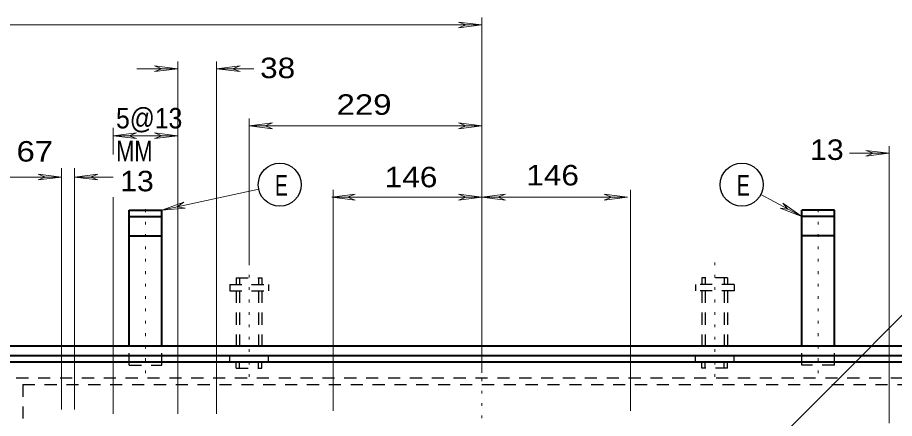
# Model space of a CAD drawing. Extents: x 312583 to 312854, y 144419 to 144597.
# Drawn here: x 312652.93 to 312685.41, y 144562.03 to 144576.9 of the extents above; entities that cross this region are included whole.
import ezdxf

# ---------------------------------------------------------------- set-up
doc = ezdxf.new("R2010")
doc.units = 0
doc.header["$LTSCALE"] = 0.3
doc.linetypes.add('DOTTED', pattern=[1.5, 0.3, -1.2])
doc.linetypes.add('SHORT_DASHED', pattern=[2.7, 1.5, -1.2])
doc.layers.add('1', color=7, linetype='Continuous', lineweight=13)

msp = doc.modelspace()

# ---------------------------------------------------------------- linework, layer by layer
at = {"layer": '1'}
for p, q in [((312670.1353, 144563.7206), (312670.1353, 144576.8996)), ((312652.0419, 144576.6236), (312670.1353, 144576.6236)), ((312669.2689, 144576.731), (312669.5449, 144576.6236)), ((312670.1353, 144576.6236), (312669.2689, 144576.731)), ((312669.2689, 144576.5163), (312669.5449, 144576.6236)), ((312670.1353, 144576.6236), (312669.2689, 144576.5163)), ((312658.8729, 144562.2026), (312658.8729, 144575.2666)), ((312660.3066, 144562.2026), (312660.3066, 144575.2666)), ((312657.3473, 144574.9983), (312658.8729, 144574.9983)), ((312658.0066, 144575.1056), (312658.2826, 144574.9983)), ((312658.8729, 144574.9983), (312658.0066, 144575.1056)), ((312658.0066, 144574.891), (312658.2826, 144574.9983)), ((312658.8729, 144574.9983), (312658.0066, 144574.891)), ((312660.3066, 144574.9983), (312661.1729, 144575.1056)), ((312660.3066, 144574.9983), (312661.6866, 144574.9983)), ((312660.3066, 144574.9983), (312661.1729, 144574.891)), ((312661.1729, 144575.1056), (312660.8969, 144574.9983)), ((312661.1729, 144574.891), (312660.8969, 144574.9983)), ((312661.5103, 144567.8146), (312661.5103, 144573.1506)), ((312661.5103, 144572.8823), (312662.3766, 144572.9896)), ((312662.3766, 144572.9896), (312662.1006, 144572.8823)), ((312669.2689, 144572.9896), (312669.5449, 144572.8823)), ((312670.1353, 144572.8823), (312669.2689, 144572.9896)), ((312656.4733, 144571.8166), (312656.4733, 144572.8133)), ((312656.4733, 144572.5143), (312657.3396, 144572.6216)), ((312657.3396, 144572.6216), (312657.0636, 144572.5143)), ((312658.0066, 144572.6216), (312658.2826, 144572.5143)), ((312658.8729, 144572.5143), (312658.0066, 144572.6216)), ((312661.5103, 144572.8823), (312670.1353, 144572.8823)), ((312661.5103, 144572.8823), (312662.3766, 144572.775)), ((312662.3766, 144572.775), (312662.1006, 144572.8823)), ((312669.2689, 144572.775), (312669.5449, 144572.8823)), ((312670.1353, 144572.8823), (312669.2689, 144572.775)), ((312656.4733, 144572.5143), (312658.8729, 144572.5143)), ((312656.4733, 144572.5143), (312657.3396, 144572.407)), ((312657.3396, 144572.407), (312657.0636, 144572.5143)), ((312658.0066, 144572.407), (312658.2826, 144572.5143)), ((312658.8729, 144572.5143), (312658.0066, 144572.407)), ((312684.3569, 144571.97), (312684.6329, 144571.8626)), ((312685.2233, 144571.8626), (312684.3569, 144571.97)), ((312685.2233, 144561.85), (312685.2233, 144572.131)), ((312683.7513, 144571.8626), (312685.2233, 144571.8626)), ((312684.3569, 144571.7553), (312684.6329, 144571.8626)), ((312685.2233, 144571.8626), (312684.3569, 144571.7553)), ((312654.5566, 144562.356), (312654.5566, 144571.3106)), ((312655.0396, 144562.356), (312655.0396, 144571.3106)), ((312653.6903, 144571.0883), (312653.9663, 144570.981)), ((312654.5566, 144570.981), (312653.6903, 144571.0883)), ((312655.0396, 144570.981), (312655.9059, 144571.0883)), ((312655.9059, 144571.0883), (312655.6299, 144570.981)), ((312652.0419, 144570.981), (312654.5566, 144570.981)), ((312653.6903, 144570.8736), (312653.9663, 144570.981)), ((312654.5566, 144570.981), (312653.6903, 144570.8736)), ((312655.0396, 144570.981), (312656.4733, 144570.981)), ((312655.0396, 144570.981), (312655.9059, 144570.8736)), ((312655.9059, 144570.8736), (312655.6299, 144570.981)), ((312661.8706, 144570.5286), (312658.2749, 144569.7543)), ((312664.5693, 144570.2373), (312665.4356, 144570.3446)), ((312664.6229, 144562.31), (312664.6229, 144570.5056)), ((312665.4356, 144570.3446), (312665.1596, 144570.2373)), ((312669.2689, 144570.3446), (312669.5449, 144570.2373)), ((312670.1353, 144570.2373), (312669.2689, 144570.3446)), ((312670.1353, 144570.2373), (312671.0016, 144570.3446)), ((312671.0016, 144570.3446), (312670.7256, 144570.2373)), ((312674.6586, 144570.3446), (312674.9346, 144570.2373)), ((312675.5249, 144570.2373), (312674.6586, 144570.3446)), ((312675.6399, 144562.31), (312675.6399, 144570.5056)), ((312656.4733, 144562.2026), (312656.4733, 144570.2296)), ((312658.2749, 144569.7543), (312659.0953, 144570.0456)), ((312659.0953, 144570.0456), (312658.8499, 144569.877)), ((312664.5693, 144570.2373), (312665.4356, 144570.13)), ((312665.4356, 144570.13), (312665.1596, 144570.2373)), ((312669.2689, 144570.13), (312669.5449, 144570.2373)), ((312670.1353, 144570.2373), (312669.2689, 144570.13)), ((312670.1353, 144570.2373), (312671.0016, 144570.13)), ((312671.0016, 144570.13), (312670.7256, 144570.2373)), ((312674.6586, 144570.13), (312674.9346, 144570.2373)), ((312675.5249, 144570.2373), (312674.6586, 144570.13)), ((312680.4623, 144570.3293), (312681.9879, 144569.5166)), ((312681.2749, 144570.015), (312681.4666, 144569.7926)), ((312681.9879, 144569.5166), (312681.2749, 144570.015)), ((312658.2749, 144569.7543), (312659.1413, 144569.831)), ((312659.1413, 144569.831), (312658.8499, 144569.877)), ((312681.1753, 144569.8233), (312681.4666, 144569.7926)), ((312681.9879, 144569.5166), (312681.1753, 144569.8233))]:
    msp.add_line(p, q, dxfattribs=at)
at = {"layer": '1', "linetype": 'DOTTED'}
for p, q in [((312657.6769, 144563.7053), (312657.6769, 144570.107)), ((312682.5936, 144563.7053), (312682.5936, 144570.107)), ((312661.5103, 144567.8146), (312661.5103, 144563.3296)), ((312678.7603, 144567.8146), (312678.7603, 144563.3296)), ((312670.1353, 144556.054), (312670.1353, 144563.7206))]:
    msp.add_line(p, q, dxfattribs=at)
at = {"layer": '1', "lineweight": 40}
for p, q in [((312657.0713, 144569.7543), (312658.2749, 144569.7543)), ((312657.0713, 144564.725), (312657.0713, 144569.7543)), ((312658.2749, 144564.725), (312658.2749, 144569.7543)), ((312683.1916, 144569.7543), (312681.9879, 144569.7543)), ((312681.9879, 144564.725), (312681.9879, 144569.7543)), ((312683.1916, 144564.725), (312683.1916, 144569.7543)), ((312657.0713, 144569.5166), (312658.2749, 144569.5166)), ((312683.1916, 144569.5166), (312681.9879, 144569.5166)), ((312657.0713, 144568.796), (312658.2749, 144568.796)), ((312683.1916, 144568.796), (312681.9879, 144568.796)), ((312651.6816, 144564.725), (312688.5813, 144564.725)), ((312652.0419, 144564.3646), (312688.2209, 144564.3646)), ((312652.2796, 144564.127), (312687.9833, 144564.127))]:
    msp.add_line(p, q, dxfattribs=at)
at = {"layer": '1', "linetype": 'SHORT_DASHED', "lineweight": 25}
for p, q in [((312661.0273, 144567.2396), (312661.9856, 144567.2396)), ((312661.0273, 144567.2396), (312661.0273, 144567.002)), ((312661.1499, 144567.2396), (312661.1499, 144567.002)), ((312661.8629, 144567.2396), (312661.8629, 144567.002)), ((312661.9856, 144567.2396), (312661.9856, 144567.002)), ((312679.2356, 144567.2396), (312678.2773, 144567.2396)), ((312678.2773, 144567.2396), (312678.2773, 144567.002)), ((312678.3999, 144567.2396), (312678.3999, 144567.002)), ((312679.1129, 144567.2396), (312679.1129, 144567.002)), ((312679.2356, 144567.2396), (312679.2356, 144567.002)), ((312660.7896, 144567.002), (312662.2233, 144567.002)), ((312660.7896, 144567.002), (312660.7896, 144566.7643)), ((312660.7896, 144566.7643), (312662.2233, 144566.7643)), ((312661.0273, 144566.7643), (312661.0273, 144564.3646)), ((312661.1499, 144566.7643), (312661.1499, 144564.3646)), ((312661.8629, 144566.7643), (312661.8629, 144564.3646)), ((312661.9856, 144566.7643), (312661.9856, 144564.3646)), ((312662.2233, 144567.002), (312662.2233, 144566.7643)), ((312679.4733, 144567.002), (312678.0396, 144567.002)), ((312678.0396, 144567.002), (312678.0396, 144566.7643)), ((312679.4733, 144566.7643), (312678.0396, 144566.7643)), ((312678.2773, 144566.7643), (312678.2773, 144564.3646)), ((312678.3999, 144566.7643), (312678.3999, 144564.3646)), ((312679.1129, 144566.7643), (312679.1129, 144564.3646)), ((312679.2356, 144566.7643), (312679.2356, 144564.3646)), ((312679.4733, 144567.002), (312679.4733, 144566.7643)), ((312657.0713, 144564.0043), (312657.0713, 144564.725)), ((312658.2749, 144564.0043), (312658.2749, 144564.725)), ((312681.9879, 144564.0043), (312681.9879, 144564.725)), ((312683.1916, 144564.0043), (312683.1916, 144564.725)), ((312660.7896, 144564.127), (312660.7896, 144564.3646)), ((312662.2233, 144564.127), (312662.2233, 144564.3646)), ((312678.0396, 144564.127), (312678.0396, 144564.3646)), ((312679.4733, 144564.127), (312679.4733, 144564.3646)), ((312657.0713, 144564.0043), (312658.2749, 144564.0043)), ((312660.7896, 144564.127), (312662.2233, 144564.127)), ((312661.0273, 144563.8893), (312661.0273, 144564.127)), ((312661.0273, 144563.8893), (312661.9856, 144563.8893)), ((312661.1499, 144563.8893), (312661.1499, 144564.127)), ((312661.8629, 144563.8893), (312661.8629, 144564.127)), ((312661.9856, 144563.8893), (312661.9856, 144564.127)), ((312679.4733, 144564.127), (312678.0396, 144564.127)), ((312678.2773, 144563.8893), (312678.2773, 144564.127)), ((312679.2356, 144563.8893), (312678.2773, 144563.8893)), ((312678.3999, 144563.8893), (312678.3999, 144564.127)), ((312679.1129, 144563.8893), (312679.1129, 144564.127)), ((312679.2356, 144563.8893), (312679.2356, 144564.127)), ((312683.1916, 144564.0043), (312681.9879, 144564.0043)), ((312652.8853, 144563.529), (312687.3853, 144563.529)), ((312653.1229, 144563.2836), (312687.1399, 144563.2836))]:
    msp.add_line(p, q, dxfattribs=at)
at = {"layer": '1'}
for points in [[(312675.1109, 144555.226), (312694.1626, 144574.3466), (312696.3246, 144574.3466)], [(312664.5693, 144570.2373), (312670.1353, 144570.2373), (312675.5249, 144570.2373)]]:
    msp.add_lwpolyline(points, dxfattribs=at)
at = {"layer": '1', "linetype": 'SHORT_DASHED', "lineweight": 25}
msp.add_lwpolyline([(312653.1229, 144563.2836), (312653.1229, 144546.5166), (312687.1399, 144546.5166)], dxfattribs=at)
at = {"layer": '1', "lineweight": 25}
for centre in [(312662.6459, 144570.6992), (312679.7569, 144570.6992)]:
    msp.add_circle(centre, 0.7964, dxfattribs=at)

# ---------------------------------------------------------------- texts
at = {"layer": '1'}
for s, width, p in [('38 ', 1.15, (312661.9165, 144574.6505)), ('229 ', 1.2, (312664.7499, 144573.2915)), ('5@13', 0.9, (312656.5803, 144572.7857)), ('67 ', 1.2, (312652.8933, 144571.5553)), ('MM', 0.8, (312656.5803, 144571.5657)), ('13 ', 1.1, (312682.2895, 144571.6174)), ('146 ', 1.15, (312666.5332, 144570.6025)), ('146 ', 1.15, (312671.7773, 144570.6714)), ('13 ', 1.1, (312656.7347, 144570.4538)), ('E', 0.7, (312662.4666, 144570.2919)), ('E', 0.7, (312679.5786, 144570.2919))]:
    msp.add_text(s, height=0.76, dxfattribs=dict(at, width=width)).set_placement(p)

doc.saveas('drawing.dxf')
